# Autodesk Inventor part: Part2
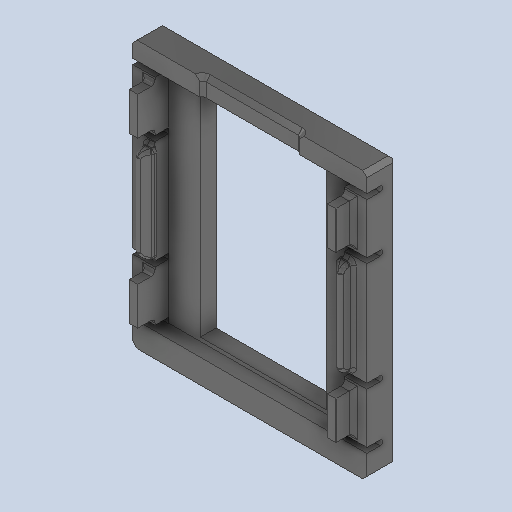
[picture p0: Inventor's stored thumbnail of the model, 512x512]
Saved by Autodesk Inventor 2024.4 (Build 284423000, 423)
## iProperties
Created: 2025-05
Part Number: Part2
Material: Generic
Document SubType Name: Modeling
Designer: AdminForWorker
Density: 1 g/cm^3
Appearance: Default
Author: AdminForWorker
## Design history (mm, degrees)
feature "Body1"
body "Solid1"
